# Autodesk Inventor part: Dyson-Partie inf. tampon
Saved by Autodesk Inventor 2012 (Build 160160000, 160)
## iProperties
Created: 2012-11
Part Number: Dyson-Partie inf. tampon
Material: Default
Document SubType Name: Modeling
Designer: Administrateur
Density: 1 g/cm^3
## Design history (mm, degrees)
node "Dyson-Partie inf. tampon1"
node "Dyson-Partie inf. tampon"
node "Base1"
